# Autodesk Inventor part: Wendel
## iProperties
Created: 2006-05
Part Number: Wendel
Document SubType Name: Blech
Designer: Scholz
Material: Stahl, weich, unlegiert
Author: Scholz
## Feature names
1. Spirale1
2. Extrusion1
3. Extrusion2
